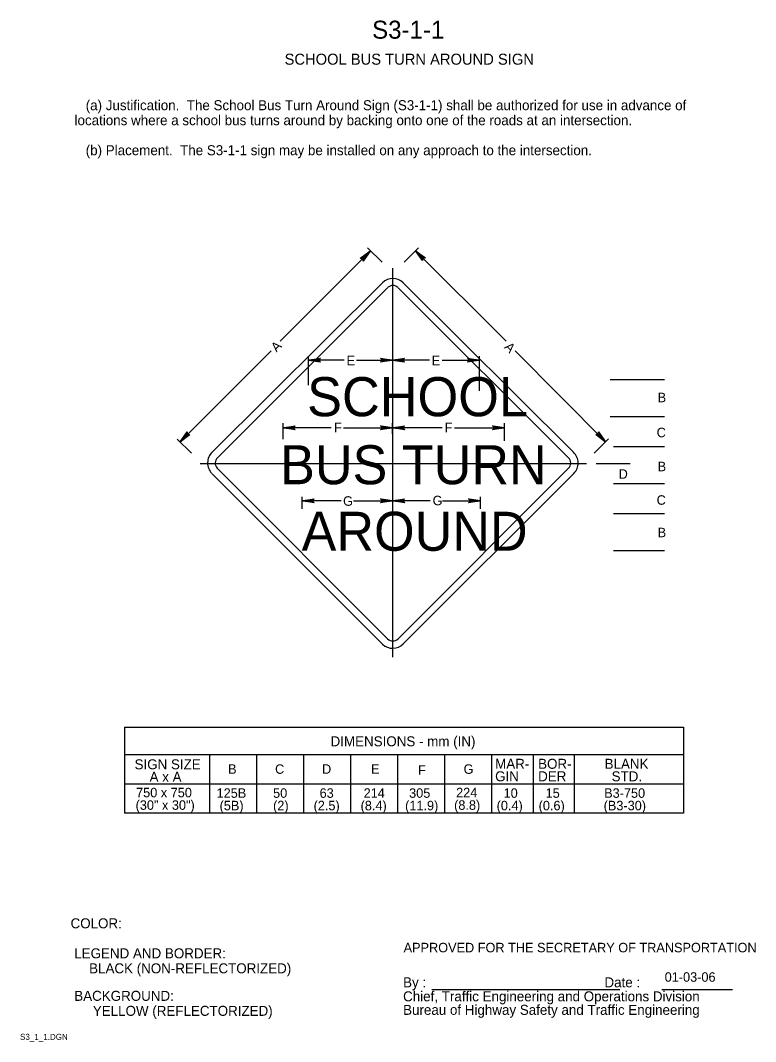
# Model space of a CAD drawing. Extents: x 0.013 to 0.196, y 0.004 to 0.259.
import ezdxf

# ---------------------------------------------------------------- set-up
doc = ezdxf.new("R2010")
doc.units = 0
for name, color, linetype in [('1', 7, 'Continuous'), ('2', 7, 'Continuous'), ('3', 7, 'Continuous'), ('4', 7, 'Continuous')]:
    doc.layers.add(name, color=color, linetype=linetype)

# ---------------------------------------------------------------- blocks, each defined once
blk = doc.blocks.new('RARROW')
at = {"layer": '3'}
for p, q in [((-2.156, 0.28500000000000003), (-2.2665, 0.384625)), ((-2.2665, 0.384625), (0, 0)), ((0, 0), (-2.2665, -0.379125)), ((-2.156, 0.28500000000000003), (-2.075625, 0.12075)), ((0, 0), (-2.156, 0.28500000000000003)), ((-2.14975, -0.2705), (0, 0)), ((-2.075625, 0.12075), (0, 0)), ((0, 0), (-2.074, -0.108)), ((-2.2665, -0.379125), (-2.14975, -0.2705)), ((-2.074, -0.108), (-2.14975, -0.2705))]:
    blk.add_line(p, q, dxfattribs=at)

msp = doc.modelspace()

# ---------------------------------------------------------------- linework, layer by layer
at = {"layer": '1'}
for p, q in [((0.173625, 0.169375), (0.16, 0.169375)), ((0.173625, 0.160125), (0.16, 0.160125)), ((0.173625, 0.152625), (0.160875, 0.152625)), ((0.134125, 0.148375), (0.0575, 0.148375)), ((0.105625, 0.148375), (0.105625, 0.148375)), ((0.105625, 0.148375), (0.105625, 0.148375)), ((0.154125, 0.148375), (0.134125, 0.148375)), ((0.165, 0.148375), (0.1565, 0.148375)), ((0.173625, 0.143375), (0.160875, 0.143375)), ((0.173625, 0.135875), (0.160875, 0.135875)), ((0.173625, 0.12662500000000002), (0.160875, 0.12662500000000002)), ((0.11543984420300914, 0.01694517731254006), (0.1624214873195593, 0.01694517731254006)), ((0.17295324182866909, 0.01694517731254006), (0.19056484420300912, 0.01694517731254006))]:
    msp.add_line(p, q, dxfattribs=at)
at = {"layer": '3'}
for p, q in [((0.10300000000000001, 0.19875), (0.099375, 0.202375)), ((0.1085, 0.19875), (0.112125, 0.202375)), ((0.0775, 0.179), (0.100125, 0.201625)), ((0.134, 0.179), (0.111375, 0.201625)), ((0.105625, 0.19725), (0.105625, 0.1)), ((0.0605, 0.15125), (0.10312500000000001, 0.193625)), ((0.061875, 0.149875), (0.104375, 0.192375)), ((0.107, 0.192375), (0.149625, 0.149875)), ((0.10825, 0.193625), (0.150875, 0.15125)), ((0.07525, 0.176625), (0.0525, 0.153875)), ((0.13625, 0.176625), (0.15887500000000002, 0.153875)), ((0.084625, 0.168), (0.084625, 0.17525000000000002)), ((0.0935, 0.17425000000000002), (0.084625, 0.17425000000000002)), ((0.096625, 0.17425000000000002), (0.105625, 0.17425000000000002)), ((0.105625, 0.17550000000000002), (0.105625, 0.17525000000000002)), ((0.114875, 0.17425000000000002), (0.105625, 0.17425000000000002)), ((0.11800000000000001, 0.17425000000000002), (0.12737500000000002, 0.17425000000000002)), ((0.12737500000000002, 0.166625), (0.12737500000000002, 0.17525000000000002)), ((0.07825, 0.1545), (0.07825, 0.1585)), ((0.105625, 0.155875), (0.105625, 0.1585)), ((0.133625, 0.154125), (0.133625, 0.1585)), ((0.09025, 0.15737500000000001), (0.07825, 0.15737500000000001)), ((0.093375, 0.15737500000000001), (0.105625, 0.15737500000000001)), ((0.11800000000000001, 0.15737500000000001), (0.105625, 0.15737500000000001)), ((0.121125, 0.15737500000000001), (0.133625, 0.15737500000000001)), ((0.055375, 0.151), (0.051750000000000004, 0.1545)), ((0.156, 0.151), (0.15962500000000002, 0.154625)), ((0.10312500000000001, 0.10325000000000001), (0.0605, 0.145875)), ((0.104375, 0.104625), (0.06175, 0.14725)), ((0.149625, 0.14725), (0.107, 0.104625)), ((0.151, 0.146), (0.10825, 0.10337500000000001)), ((0.083, 0.137125), (0.083, 0.140125)), ((0.09275, 0.139125), (0.083, 0.139125)), ((0.095875, 0.139125), (0.105625, 0.139125)), ((0.105625, 0.14025), (0.105625, 0.140125)), ((0.115, 0.139125), (0.105625, 0.139125)), ((0.11812500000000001, 0.139125), (0.12762500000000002, 0.139125)), ((0.12762500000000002, 0.137125), (0.12762500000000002, 0.140125)), ((0.038625, 0.0825), (0.178375, 0.0825)), ((0.038625, 0.0825), (0.038625, 0.061)), ((0.178375, 0.0825), (0.178375, 0.061)), ((0.178375, 0.075625), (0.038625, 0.075625)), ((0.059875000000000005, 0.07575), (0.059875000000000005, 0.061)), ((0.07162500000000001, 0.075625), (0.07162500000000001, 0.061)), ((0.083375, 0.075625), (0.083375, 0.061)), ((0.095125, 0.075625), (0.095125, 0.061)), ((0.106875, 0.075625), (0.106875, 0.061)), ((0.11862500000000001, 0.075625), (0.11862500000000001, 0.061)), ((0.130375, 0.075625), (0.130375, 0.061)), ((0.130375, 0.075625), (0.130375, 0.06225)), ((0.14075000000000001, 0.07575), (0.14075000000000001, 0.061)), ((0.151, 0.075625), (0.151, 0.061)), ((0.178375, 0.06825), (0.038625, 0.06825)), ((0.178375, 0.061), (0.038625, 0.061))]:
    msp.add_line(p, q, dxfattribs=at)
for centre, radius, start, end in [((0.10568750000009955, 0.19105909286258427), 0.003626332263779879, 45.03806666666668, 134.96193611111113), ((0.10569511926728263, 0.19107560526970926), 0.0018664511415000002, 45.03657222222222, 134.96044166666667), ((0.06311040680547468, 0.14857567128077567), 0.003732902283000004, 133.40603611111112, 225), ((0.14828904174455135, 0.14857109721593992), 0.0037233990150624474, 315.50790555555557, 46.011380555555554), ((0.06310643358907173, 0.148524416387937), 0.001827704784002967, 132.35789722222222, 223.9518611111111), ((0.14833975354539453, 0.14857807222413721), 0.0018258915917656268, 314.7557194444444, 45.25919444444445), ((0.1056239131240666, 0.10591956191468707), 0.003656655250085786, 226.8910611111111, 315.9033), ((0.1056874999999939, 0.10596032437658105), 0.0018723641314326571, 225.4938805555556, 314.5061194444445)]:
    msp.add_arc(centre, radius, start, end, dxfattribs=at)

# ---------------------------------------------------------------- block references
at = {"layer": '3', "xscale": 0.0013236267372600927}
for p, yscale, rotation in [((0.1, 0.2015), 0.0013093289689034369, 45.093773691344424), ((0.111375, 0.201625), 0.0013093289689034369, 134.9062263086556), ((0.084625, 0.17425000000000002), 0.001309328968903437, 180), ((0.105625, 0.17425000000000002), 0.001309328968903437, 180), ((0.0525, 0.153875), 0.0013093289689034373, -134.90622630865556), ((0.07825, 0.15737500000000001), 0.001309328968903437, 180), ((0.105625, 0.15737500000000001), 0.001309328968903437, 180), ((0.15887500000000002, 0.153875), 0.0013093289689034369, -45.093773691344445), ((0.083, 0.139125), 0.001309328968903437, 180), ((0.105625, 0.139125), 0.001309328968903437, 180)]:
    msp.add_blockref('RARROW', p, dxfattribs=dict(at, yscale=yscale, rotation=rotation))
at = {"layer": '3', "xscale": 0.0013236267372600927, "yscale": 0.001309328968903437}
for p in [(0.105625, 0.17425000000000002), (0.12737500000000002, 0.17425000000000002), (0.105625, 0.15737500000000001), (0.133625, 0.15737500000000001), (0.105625, 0.139125), (0.12762500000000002, 0.139125)]:
    msp.add_blockref('RARROW', p, dxfattribs=at)

# ---------------------------------------------------------------- texts
at = {"layer": '1'}
for s, height, p in [('S3-1-1', 0.0045000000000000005, (0.1005, 0.254625)), ('SCHOOL BUS TURN AROUND SIGN', 0.00275025, (0.078625, 0.248125)), ('COLOR:', 0.0024997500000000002, (0.025125, 0.03225)), ('APPROVED FOR THE SECRETARY OF TRANSPORTATION', 0.0023752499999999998, (0.108375, 0.02625)), (' LEGEND AND BORDER:', 0.0024997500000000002, (0.025125, 0.02475)), ('     BLACK (NON-REFLECTORIZED)', 0.0024997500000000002, (0.025125, 0.021)), ('By :                                                Date :', 0.0024997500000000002, (0.10825, 0.0175)), (' BACKGROUND:', 0.0024997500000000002, (0.025125, 0.014125)), ('Chief, Traffic Engineering and Operations Division', 0.0024997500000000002, (0.10825, 0.014)), ('      YELLOW (REFLECTORIZED)', 0.0024997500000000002, (0.025125, 0.010375)), ('Bureau of Highway Safety and Traffic Engineering', 0.0024997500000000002, (0.10825, 0.010625)), ('S3_1_1.DGN', 0.0015, (0.0125, 0.004375))]:
    msp.add_text(s, height=height, dxfattribs=at).set_placement(p)
at = {"layer": '2'}
for s, p in [('   (a) Justification.  The School Bus Turn Around Sign (S3-1-1) shall be authorized for use in advance of ', (0.026125, 0.23675000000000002)), ('locations where a school bus turns around by backing onto one of the roads at an intersection.', (0.026125, 0.233)), ('   (b) Placement.  The S3-1-1 sign may be installed on any approach to the intersection.', (0.026125, 0.2255))]:
    msp.add_text(s, height=0.0024997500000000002, dxfattribs=at).set_placement(p)
at = {"layer": '3'}
for rotation, p in [(45.093775, (0.076625, 0.176125)), (314.906225, (0.133375, 0.177375))]:
    msp.add_text('A', height=0.0023752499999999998, rotation=rotation, dxfattribs=at).set_placement(p)
for s, height, p in [('E', 0.0023752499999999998, (0.094125, 0.17300000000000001)), ('E', 0.0023752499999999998, (0.115375, 0.17300000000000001)), ('SCHOOL', 0.009777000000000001, (0.08425, 0.16025)), ('B', 0.0023752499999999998, (0.171875, 0.16375)), ('F', 0.0023752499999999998, (0.091, 0.15625)), ('F', 0.0023752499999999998, (0.11862500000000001, 0.15625)), ('C', 0.0023752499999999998, (0.171625, 0.155)), ('BUS TURN', 0.00975, (0.0775, 0.14325000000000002)), ('B', 0.0023752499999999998, (0.171875, 0.1465)), ('D', 0.0023752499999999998, (0.162125, 0.144625)), ('G', 0.0023752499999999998, (0.115625, 0.138)), ('C', 0.0023752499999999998, (0.171625, 0.138125)), ('G', 0.0023752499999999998, (0.09325, 0.137875)), ('AROUND', 0.00975, (0.082875, 0.12662500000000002)), ('B', 0.0023752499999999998, (0.171875, 0.13)), ('DIMENSIONS - mm (IN)', 0.0024997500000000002, (0.090125, 0.07775)), ('SIGN SIZE', 0.0024997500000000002, (0.041125, 0.07200000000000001)), ('MAR-', 0.0024997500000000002, (0.13125, 0.072125)), ('BOR-', 0.0024997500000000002, (0.14200000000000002, 0.072125)), ('BLANK', 0.0024997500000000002, (0.15862500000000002, 0.072125)), ('B', 0.0023752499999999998, (0.0645, 0.07087500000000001)), ('C', 0.0023752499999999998, (0.07625, 0.07087500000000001)), ('D', 0.0023752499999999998, (0.088, 0.07087500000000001)), ('E', 0.0023752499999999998, (0.10025, 0.07087500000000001)), ('F', 0.0023752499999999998, (0.112, 0.07062500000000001)), ('G', 0.0023752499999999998, (0.123375, 0.07087500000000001)), ('GIN', 0.0024997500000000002, (0.13125, 0.069)), ('DER', 0.0024997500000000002, (0.14200000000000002, 0.069)), ('STD.', 0.0024997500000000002, (0.160375, 0.069)), ('A x A', 0.0024997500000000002, (0.044875, 0.068875)), ('750 x 750', 0.0023752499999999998, (0.0415, 0.065)), ('125B', 0.0023752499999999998, (0.061625, 0.064875)), ('50', 0.0023752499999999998, (0.07575, 0.064875)), ('63', 0.0023752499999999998, (0.08737500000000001, 0.064875)), ('214', 0.0023752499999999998, (0.098375, 0.064875)), ('305', 0.0023752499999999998, (0.10975, 0.064875)), ('224', 0.0023752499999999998, (0.1215, 0.065)), ('10', 0.0023752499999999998, (0.133375, 0.064875)), ('15', 0.0023752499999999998, (0.143875, 0.064875)), ('B3-750', 0.0023752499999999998, (0.1585, 0.064875)), ('(30" x 30")', 0.0023752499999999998, (0.041375, 0.061875)), ('(5B)', 0.0023752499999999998, (0.062375, 0.06175)), ('(2)', 0.0023752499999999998, (0.07575, 0.06175)), ('(2.5)', 0.0023752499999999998, (0.085875, 0.06175)), ('(8.4)', 0.0023752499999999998, (0.097625, 0.06175)), ('(11.9)', 0.0023752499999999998, (0.10875, 0.06175)), ('(8.8)', 0.0023752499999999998, (0.121, 0.061875)), ('(0.4)', 0.0023752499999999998, (0.131625, 0.06175)), ('(0.6)', 0.0023752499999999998, (0.142125, 0.06175)), ('(B3-30)', 0.0023752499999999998, (0.15837500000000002, 0.06175))]:
    msp.add_text(s, height=height, dxfattribs=at).set_placement(p)
at = {"layer": '4'}
msp.add_text('01-03-06', height=0.0023752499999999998, dxfattribs=at).set_placement((0.17363605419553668, 0.018894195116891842))

doc.saveas('drawing.dxf')
